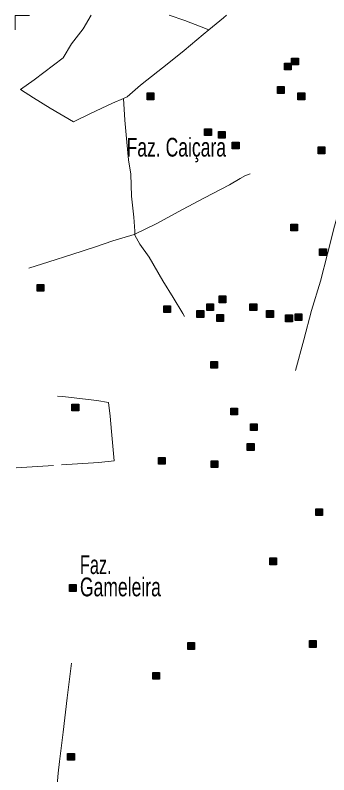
# Model space of a CAD drawing. Extents: x 445.6 to 500, y 8618.1 to 8673.4.
# Drawn here: x 445.57 to 448.24, y 8666.9 to 8673.38 of the extents above; entities that cross this region are included whole.
import ezdxf

# ---------------------------------------------------------------- set-up
doc = ezdxf.new("R2010")
doc.units = 0
doc.header["$LTSCALE"] = 0.064
doc.linetypes.add('DOT_DASHED', pattern=[7.7, 5, -1.2, 0.3, -1.2])
for name, color, linetype, lineweight in [('2', 7, 'Continuous', 25), ('22', 7, 'DOT_DASHED', 13), ('63', 7, 'Continuous', 13)]:
    doc.layers.add(name, color=color, linetype=linetype, lineweight=lineweight)
doc.layers.add('61', color=7, linetype='Continuous')

msp = doc.modelspace()

# ---------------------------------------------------------------- hatches: boundary and pattern name
at = {"layer": '2'}
for points in [[(447.9272, 8673.0186), (447.9852, 8673.0186), (447.9852, 8672.9606), (447.9272, 8672.9606)], [(447.8664, 8672.9746), (447.9244, 8672.9746), (447.9244, 8672.9166), (447.8664, 8672.9166)], [(447.8056, 8672.7747), (447.8636, 8672.7747), (447.8636, 8672.7167), (447.8056, 8672.7167)], [(446.693, 8672.7203), (446.751, 8672.7203), (446.751, 8672.6623), (446.693, 8672.6623)], [(447.9813, 8672.7205), (448.0393, 8672.7205), (448.0393, 8672.6625), (447.9813, 8672.6625)], [(447.1841, 8672.4156), (447.2421, 8672.4156), (447.2421, 8672.3576), (447.1841, 8672.3576)], [(447.3023, 8672.3918), (447.3603, 8672.3918), (447.3603, 8672.3338), (447.3023, 8672.3338)], [(447.4206, 8672.3004), (447.4786, 8672.3004), (447.4786, 8672.2424), (447.4206, 8672.2424)], [(448.1536, 8672.2597), (448.2116, 8672.2597), (448.2116, 8672.2017), (448.1536, 8672.2017)], [(447.9194, 8671.6016), (447.9774, 8671.6016), (447.9774, 8671.5436), (447.9194, 8671.5436)], [(448.166, 8671.3915), (448.224, 8671.3915), (448.224, 8671.3335), (448.166, 8671.3335)], [(445.7542, 8671.0866), (445.8122, 8671.0866), (445.8122, 8671.0286), (445.7542, 8671.0286)], [(447.308, 8670.9884), (447.366, 8670.9884), (447.366, 8670.9304), (447.308, 8670.9304)], [(446.8351, 8670.9037), (446.8931, 8670.9037), (446.8931, 8670.8457), (446.8351, 8670.8457)], [(447.2033, 8670.9206), (447.2613, 8670.9206), (447.2613, 8670.8626), (447.2033, 8670.8626)], [(447.5715, 8670.9206), (447.6295, 8670.9206), (447.6295, 8670.8626), (447.5715, 8670.8626)], [(447.1188, 8670.863), (447.1768, 8670.863), (447.1768, 8670.805), (447.1188, 8670.805)], [(447.2877, 8670.8291), (447.3457, 8670.8291), (447.3457, 8670.7711), (447.2877, 8670.7711)], [(447.7133, 8670.863), (447.7713, 8670.863), (447.7713, 8670.805), (447.7133, 8670.805)], [(447.8755, 8670.8258), (447.9335, 8670.8258), (447.9335, 8670.7678), (447.8755, 8670.7678)], [(447.9565, 8670.8359), (448.0145, 8670.8359), (448.0145, 8670.7779), (447.9565, 8670.7779)], [(447.2371, 8670.4294), (447.2951, 8670.4294), (447.2951, 8670.3714), (447.2371, 8670.3714)], [(446.0516, 8670.0649), (446.1096, 8670.0649), (446.1096, 8670.0069), (446.0516, 8670.0069)], [(447.4086, 8670.0312), (447.4666, 8670.0312), (447.4666, 8669.9732), (447.4086, 8669.9732)], [(447.5758, 8669.8972), (447.6338, 8669.8972), (447.6338, 8669.8392), (447.5758, 8669.8392)], [(447.5488, 8669.7278), (447.6068, 8669.7278), (447.6068, 8669.6698), (447.5488, 8669.6698)], [(446.7907, 8669.6093), (446.8487, 8669.6093), (446.8487, 8669.5513), (446.7907, 8669.5513)], [(447.2397, 8669.5821), (447.2977, 8669.5821), (447.2977, 8669.5241), (447.2397, 8669.5241)], [(448.1332, 8669.1722), (448.1912, 8669.1722), (448.1912, 8669.1142), (448.1332, 8669.1142)], [(447.7414, 8668.7521), (447.7994, 8668.7521), (447.7994, 8668.6941), (447.7414, 8668.6941)], [(446.0307, 8668.5251), (446.0887, 8668.5251), (446.0887, 8668.4671), (446.0307, 8668.4671)], [(447.0405, 8668.0297), (447.0985, 8668.0297), (447.0985, 8667.9717), (447.0405, 8667.9717)], [(448.0798, 8668.0467), (448.1378, 8668.0467), (448.1378, 8667.9887), (448.0798, 8667.9887)], [(446.7414, 8667.7756), (446.7994, 8667.7756), (446.7994, 8667.7176), (446.7414, 8667.7176)], [(446.0152, 8667.0844), (446.0732, 8667.0844), (446.0732, 8667.0264), (446.0152, 8667.0264)]]:
    msp.add_hatch(color=256, dxfattribs=at).paths.add_polyline_path(points)

# ---------------------------------------------------------------- linework, layer by layer
for points in [[(447.9272, 8673.0186), (447.9852, 8673.0186), (447.9852, 8672.9606), (447.9272, 8672.9606)], [(447.8664, 8672.9746), (447.9244, 8672.9746), (447.9244, 8672.9166), (447.8664, 8672.9166)], [(447.8056, 8672.7747), (447.8636, 8672.7747), (447.8636, 8672.7167), (447.8056, 8672.7167)], [(446.693, 8672.7203), (446.751, 8672.7203), (446.751, 8672.6623), (446.693, 8672.6623)], [(447.9813, 8672.7205), (448.0393, 8672.7205), (448.0393, 8672.6625), (447.9813, 8672.6625)], [(447.1841, 8672.4156), (447.2421, 8672.4156), (447.2421, 8672.3576), (447.1841, 8672.3576)], [(447.3023, 8672.3918), (447.3603, 8672.3918), (447.3603, 8672.3338), (447.3023, 8672.3338)], [(447.4206, 8672.3004), (447.4786, 8672.3004), (447.4786, 8672.2424), (447.4206, 8672.2424)], [(448.1536, 8672.2597), (448.2116, 8672.2597), (448.2116, 8672.2017), (448.1536, 8672.2017)], [(447.9194, 8671.6016), (447.9774, 8671.6016), (447.9774, 8671.5436), (447.9194, 8671.5436)], [(448.166, 8671.3915), (448.224, 8671.3915), (448.224, 8671.3335), (448.166, 8671.3335)], [(445.7542, 8671.0866), (445.8122, 8671.0866), (445.8122, 8671.0286), (445.7542, 8671.0286)], [(447.308, 8670.9884), (447.366, 8670.9884), (447.366, 8670.9304), (447.308, 8670.9304)], [(446.8351, 8670.9037), (446.8931, 8670.9037), (446.8931, 8670.8457), (446.8351, 8670.8457)], [(447.2033, 8670.9206), (447.2613, 8670.9206), (447.2613, 8670.8626), (447.2033, 8670.8626)], [(447.5715, 8670.9206), (447.6295, 8670.9206), (447.6295, 8670.8626), (447.5715, 8670.8626)], [(447.1188, 8670.863), (447.1768, 8670.863), (447.1768, 8670.805), (447.1188, 8670.805)], [(447.2877, 8670.8291), (447.3457, 8670.8291), (447.3457, 8670.7711), (447.2877, 8670.7711)], [(447.7133, 8670.863), (447.7713, 8670.863), (447.7713, 8670.805), (447.7133, 8670.805)], [(447.8755, 8670.8258), (447.9335, 8670.8258), (447.9335, 8670.7678), (447.8755, 8670.7678)], [(447.9565, 8670.8359), (448.0145, 8670.8359), (448.0145, 8670.7779), (447.9565, 8670.7779)], [(447.2371, 8670.4294), (447.2951, 8670.4294), (447.2951, 8670.3714), (447.2371, 8670.3714)], [(446.0516, 8670.0649), (446.1096, 8670.0649), (446.1096, 8670.0069), (446.0516, 8670.0069)], [(447.4086, 8670.0312), (447.4666, 8670.0312), (447.4666, 8669.9732), (447.4086, 8669.9732)], [(447.5758, 8669.8972), (447.6338, 8669.8972), (447.6338, 8669.8392), (447.5758, 8669.8392)], [(447.5488, 8669.7278), (447.6068, 8669.7278), (447.6068, 8669.6698), (447.5488, 8669.6698)], [(446.7907, 8669.6093), (446.8487, 8669.6093), (446.8487, 8669.5513), (446.7907, 8669.5513)], [(447.2397, 8669.5821), (447.2977, 8669.5821), (447.2977, 8669.5241), (447.2397, 8669.5241)], [(448.1332, 8669.1722), (448.1912, 8669.1722), (448.1912, 8669.1142), (448.1332, 8669.1142)], [(447.7414, 8668.7521), (447.7994, 8668.7521), (447.7994, 8668.6941), (447.7414, 8668.6941)], [(446.0307, 8668.5251), (446.0887, 8668.5251), (446.0887, 8668.4671), (446.0307, 8668.4671)], [(447.0405, 8668.0297), (447.0985, 8668.0297), (447.0985, 8667.9717), (447.0405, 8667.9717)], [(448.0798, 8668.0467), (448.1378, 8668.0467), (448.1378, 8667.9887), (448.0798, 8667.9887)], [(446.7414, 8667.7756), (446.7994, 8667.7756), (446.7994, 8667.7176), (446.7414, 8667.7176)], [(446.0152, 8667.0844), (446.0732, 8667.0844), (446.0732, 8667.0264), (446.0152, 8667.0264)]]:
    msp.add_lwpolyline(points, close=True, dxfattribs=at)
at = {"layer": '22'}
for points in [[(446.4912, 8672.6739), (446.3993, 8672.6319), (446.2111, 8672.5439), (446.0649, 8672.4739), (445.8667, 8672.5919), (445.7225, 8672.6779), (445.6124, 8672.7499), (445.7305, 8672.8338), (445.9771, 8673.0189), (446.0492, 8673.1389), (446.1473, 8673.2689), (446.2165, 8673.3829)], [(447.2218, 8673.2597), (447.1542, 8673.2836), (447.016, 8673.3396), (446.8815, 8673.3841)], [(447.2218, 8673.2597), (447.3464, 8673.3616), (447.3705, 8673.3833)], [(446.4912, 8672.6739), (446.5227, 8672.6883), (446.6368, 8672.7883), (446.8791, 8672.9783), (447.0113, 8673.0822), (447.1735, 8673.2202), (447.2218, 8673.2597)], [(446.4912, 8672.6739), (446.5032, 8672.4892), (446.522, 8672.2998), (446.5347, 8672.1506), (446.5534, 8672.0278), (446.5597, 8671.8404), (446.5804, 8671.6602), (446.5888, 8671.5415), (446.5888, 8671.5139)], [(446.5888, 8671.5139), (446.7714, 8671.603), (446.9955, 8671.7247), (447.1832, 8671.8267), (447.3979, 8671.9371), (447.4875, 8671.9912), (447.5343, 8672.015), (447.5728, 8672.0307)], [(447.9595, 8670.3504), (448.0318, 8670.6125), (448.098, 8670.8625), (448.173, 8671.1145), (448.2334, 8671.3473), (448.2938, 8671.5829), (448.3363, 8671.7342)], [(445.6838, 8671.2239), (445.8541, 8671.2803), (446.05, 8671.3427), (446.2543, 8671.4073), (446.4024, 8671.4572), (446.5837, 8671.5114), (446.5888, 8671.5139)], [(446.5888, 8671.5139), (446.5888, 8671.5082), (446.6326, 8671.4291), (446.7118, 8671.3188), (446.8266, 8671.1178), (446.9162, 8670.9762), (446.9979, 8670.8377), (447.0127, 8670.8122)], [(445.5747, 8669.5217), (445.9616, 8669.5454), (446.2828, 8669.5664), (446.4117, 8669.5822), (446.3907, 8669.8319), (446.3775, 8669.9607), (446.3651, 8670.0778), (446.2651, 8670.0962), (446.0466, 8670.1225), (445.9755, 8670.1304), (445.9282, 8670.1335)], [(446.0474, 8667.8544), (446.0106, 8667.5583), (445.9776, 8667.2653), (445.9445, 8667.0157), (445.9353, 8666.9147), (445.9186, 8666.741), (445.8966, 8666.5887), (445.88, 8666.4877), (445.8541, 8666.3433), (445.8247, 8666.1432), (445.8119, 8666.0239), (445.7972, 8665.9053), (445.7806, 8665.7713), (445.7794, 8665.6713)]]:
    msp.add_lwpolyline(points, dxfattribs=at)
at = {"layer": '63'}
msp.add_lwpolyline([(445.6908, 8673.3817), (445.5676, 8673.3817), (445.5676, 8673.2603)], dxfattribs=at)

# ---------------------------------------------------------------- texts
at = {"layer": '61'}
for s, width, p in [('Faz. Caiçara', 0.7, (446.5187, 8672.1773)), ('Faz.', 0.65, (446.1202, 8668.6146)), ('Gameleira', 0.7, (446.1202, 8668.4246))]:
    msp.add_text(s, height=0.16, dxfattribs=dict(at, width=width)).set_placement(p)

doc.saveas('drawing.dxf')
